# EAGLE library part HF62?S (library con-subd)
SUB-D
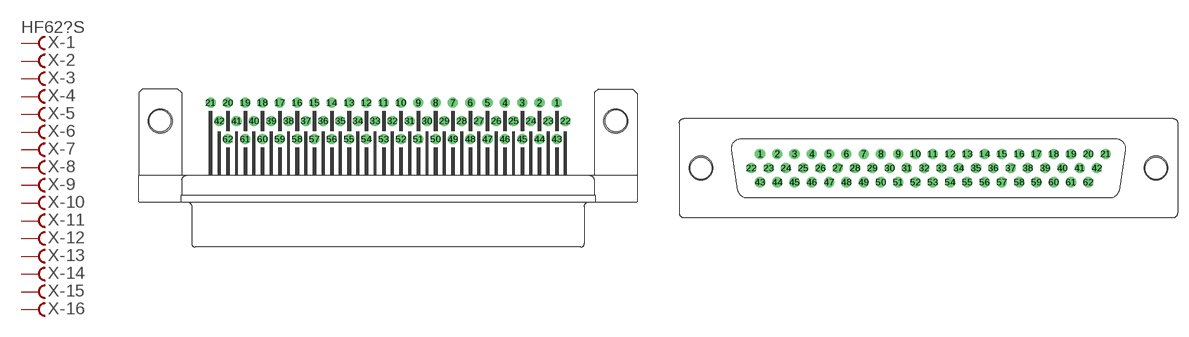
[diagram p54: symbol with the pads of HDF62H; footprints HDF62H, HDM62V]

Designator prefix X; gates -1=FV -2=F -3=F -4=F -5=F -6=F -7=F -8=F -9=F -10=F -11=F -12=F -13=F -14=F -15=F -16=F -17=F -18=F -19=F -20=F -21=F -22=F -23=F -24=F -25=F -26=F -27=F -28=F -29=F -30=F -31=F -32=F -33=F -34=F -35=F -36=F -37=F -38=F -39=F -40=F -41=F -42=F -43=F -44=F -45=F -46=F -47=F -48=F -49=F -50=F -51=F -52=F -53=F -54=F -55=F -56=F -57=F -58=F -59=F -60=F -61=F -62=F

## HF62HS (OC_FARNELL: unknown; OC_NEWARK: unknown)  [HDF62H]
1  -1:F  pas
2  -2:F  pas
3  -3:F  pas
4  -4:F  pas
5  -5:F  pas
6  -6:F  pas
7  -7:F  pas
8  -8:F  pas
9  -9:F  pas
10  -10:F  pas
11  -11:F  pas
12  -12:F  pas
13  -13:F  pas
14  -14:F  pas
15  -15:F  pas
16  -16:F  pas
17  -17:F  pas
18  -18:F  pas
19  -19:F  pas
20  -20:F  pas
21  -21:F  pas
22  -22:F  pas
23  -23:F  pas
24  -24:F  pas
25  -25:F  pas
26  -26:F  pas
27  -27:F  pas
28  -28:F  pas
29  -29:F  pas
30  -30:F  pas
31  -31:F  pas
32  -32:F  pas
33  -33:F  pas
34  -34:F  pas
35  -35:F  pas
36  -36:F  pas
37  -37:F  pas
38  -38:F  pas
39  -39:F  pas
40  -40:F  pas
41  -41:F  pas
42  -42:F  pas
43  -43:F  pas
44  -44:F  pas
45  -45:F  pas
46  -46:F  pas
47  -47:F  pas
48  -48:F  pas
49  -49:F  pas
50  -50:F  pas
51  -51:F  pas
52  -52:F  pas
53  -53:F  pas
54  -54:F  pas
55  -55:F  pas
56  -56:F  pas
57  -57:F  pas
58  -58:F  pas
59  -59:F  pas
60  -60:F  pas
61  -61:F  pas
62  -62:F  pas

## HF62VS (OC_FARNELL: unknown; OC_NEWARK: unknown)  [HDM62V]
Pads as for HDF62H

## Footprint HDF62H (pad centres in mm)
SUB-D
drill 0.9 octagon: 1 23.527,2.54
drill 0.9 round: 2 21.114,2.54; 3 18.701,2.54; 4 16.288,2.54; 5 13.875,2.54; 6 11.462,2.54; 7 9.049,2.54; 8 6.636,2.54; 9 4.223,2.54; 10 1.81,2.54; 11 -0.603,2.54; 12 -3.016,2.54; 13 -5.429,2.54; 14 -7.842,2.54; 15 -10.255,2.54; 16 -12.668,2.54; 17 -15.081,2.54; 18 -17.494,2.54; 19 -19.907,2.54; 20 -22.32,2.54; 21 -24.733,2.54; 22 24.734,0; 23 22.321,0; 24 19.908,0; 25 17.495,0; 26 15.082,0; 27 12.669,0; 28 10.256,0; 29 7.843,0; 30 5.43,0; 31 3.017,0; 32 0.604,0; 33 -1.809,0; 34 -4.222,0; 35 -6.635,0; 36 -9.048,0; 37 -11.461,0; 38 -13.874,0; 39 -16.287,0; 40 -18.7,0; 41 -21.113,0; 42 -23.526,0; 43 23.527,-2.54; 44 21.114,-2.54; 45 18.701,-2.54; 46 16.288,-2.54; 47 13.875,-2.54; 48 11.462,-2.54; 49 9.049,-2.54; 50 6.636,-2.54; 51 4.223,-2.54; 52 1.81,-2.54; 53 -0.603,-2.54; 54 -3.016,-2.54; 55 -5.429,-2.54; 56 -7.842,-2.54; 57 -10.255,-2.54; 58 -12.668,-2.54; 59 -15.081,-2.54; 60 -17.494,-2.54; 61 -19.907,-2.54; 62 -22.32,-2.54
hole 3 at -31.75,0
hole 3 at 31.75,0

## Footprint HDM62V (pad centres in mm)
SUB-D
drill 0.9 round: 1 -23.532,1.98; 2 -21.119,1.98; 3 -18.706,1.98; 4 -16.293,1.98; 5 -13.88,1.98; 6 -11.467,1.98; 7 -9.054,1.98; 8 -6.641,1.98; 9 -4.228,1.98; 10 -1.815,1.98; 11 0.598,1.98; 12 3.011,1.98; 13 5.424,1.98; 14 7.837,1.98; 15 10.25,1.98; 16 12.663,1.98; 17 15.076,1.98; 18 17.489,1.98; 19 19.902,1.98; 20 22.315,1.98; 21 24.728,1.98; 22 -24.739,0; 23 -22.325,0; 24 -19.912,0; 25 -17.499,0; 26 -15.086,0; 27 -12.673,0; 28 -10.26,0; 29 -7.847,0; 30 -5.434,0; 31 -3.021,0; 32 -0.608,0; 33 1.805,0; 34 4.218,0; 35 6.631,0; 36 9.044,0; 37 11.457,0; 38 13.87,0; 39 16.283,0; 40 18.696,0; 41 21.109,0; 42 23.522,0; 43 -23.532,-1.98; 44 -21.119,-1.98; 45 -18.706,-1.98; 46 -16.293,-1.98; 47 -13.88,-1.98; 48 -11.467,-1.98; 49 -9.054,-1.98; 50 -6.641,-1.98; 51 -4.228,-1.98; 52 -1.815,-1.98; 53 0.598,-1.98; 54 3.011,-1.98; 55 5.424,-1.98; 56 7.837,-1.98; 57 10.25,-1.98; 58 12.663,-1.98; 59 15.076,-1.98; 60 17.489,-1.98; 61 19.902,-1.98; 62 22.315,-1.98
hole 3 at -31.75,0
hole 3 at 31.75,0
